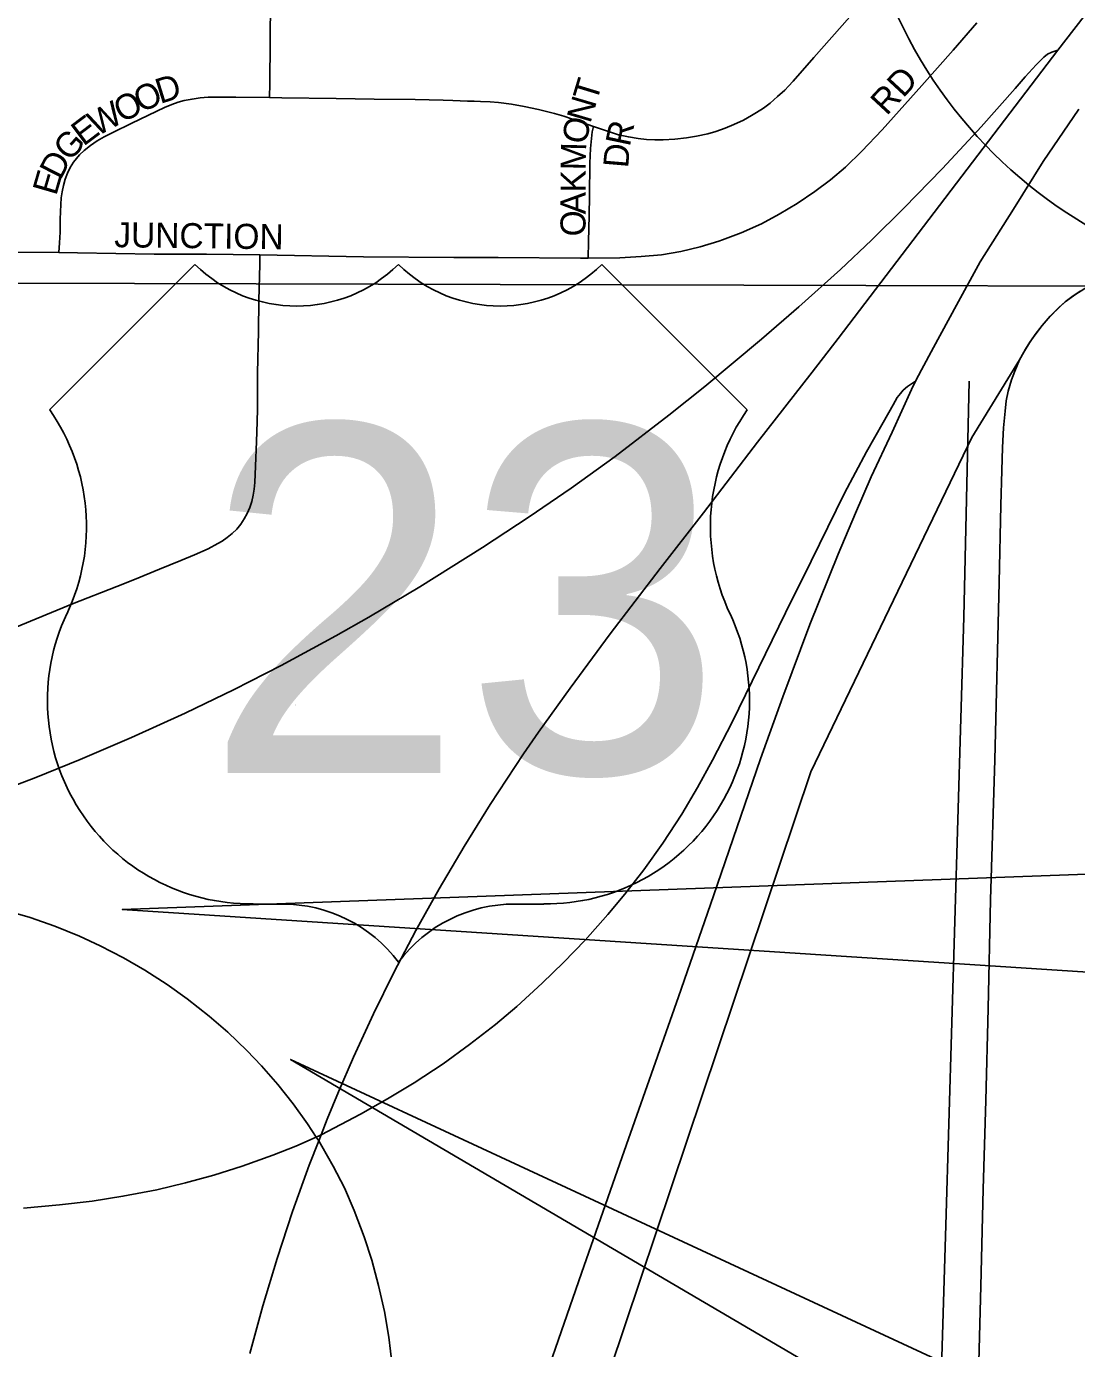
# Model space of a CAD drawing. Extents: x -5.6 to 34, y 0 to 22.
# Drawn here: x 5.62 to 6.458, y 18.084 to 19.139 of the extents above; entities that cross this region are included whole.
import ezdxf

# ---------------------------------------------------------------- set-up
doc = ezdxf.new("R2010")
doc.units = 0
for name, color, linetype in [('GM_X_City_Street', 7, 'Continuous'), ('GM_X_City_Street_Text', 7, 'Continuous'), ('GM_X_Corporation', 7, 'Continuous'), ('GM_X_Interstate_Route', 7, 'Continuous'), ('GM_X_Interstate_Shield', 7, 'Continuous'), ('GM_X_Minor_River', 7, 'Continuous'), ('GM_X_Section', 7, 'Continuous'), ('GM_X_Township_Road', 7, 'Continuous'), ('GM_X_US_Location', 7, 'Continuous'), ('GM_X_US_Route', 7, 'Continuous'), ('GM_X_US_Shield', 7, 'Continuous'), ('SH_Text', 7, 'Continuous')]:
    doc.layers.add(name, color=color, linetype=linetype)

msp = doc.modelspace()

# ---------------------------------------------------------------- linework, layer by layer
at = {"layer": 'GM_X_City_Street'}
for points in [[(5.8141, 19.0825), (5.8142, 19.0939), (5.8149, 19.1602), (5.8153, 19.1877), (5.8156, 19.1996), (5.8158, 19.204), (5.8162, 19.2074), (5.817, 19.2116), (5.8182, 19.2169), (5.8217, 19.2289)], [(6.0727, 19.0594), (6.0927, 19.0529), (6.1005, 19.0511), (6.1084, 19.0498), (6.115, 19.0491), (6.1217, 19.0488), (6.1284, 19.0489), (6.1376, 19.0494), (6.1469, 19.0504), (6.1548, 19.0517), (6.1639, 19.0536), (6.1703, 19.0554), (6.1777, 19.058), (6.1846, 19.0611), (6.1925, 19.0645), (6.1987, 19.0682), (6.2029, 19.0706), (6.2085, 19.0741), (6.2137, 19.0782), (6.2197, 19.0835), (6.2254, 19.0885), (6.2284, 19.0917), (6.2321, 19.0956), (6.2486, 19.1145), (6.2772, 19.147)], [(6.1727, 18.968), (6.1758, 18.9689), (6.1906, 18.9745), (6.2068, 18.9817), (6.2208, 18.9894), (6.2354, 18.998), (6.2495, 19.0075), (6.2619, 19.0169), (6.2738, 19.0271), (6.287, 19.0398), (6.3032, 19.0568), (6.3347, 19.0921), (6.3599, 19.1205), (6.3787, 19.1423)], [(5.6459, 18.9588), (5.6464, 18.9667), (5.6469, 18.975), (5.6469, 18.9855), (5.6473, 18.9972), (5.6477, 19.0024), (5.6484, 19.0074), (5.6495, 19.0124), (5.6509, 19.0173), (5.6527, 19.0221), (5.6549, 19.0267), (5.6575, 19.031), (5.6598, 19.034), (5.6623, 19.0368), (5.666, 19.0403), (5.671, 19.0442), (5.6763, 19.0479), (5.6819, 19.0511), (5.6888, 19.0547), (5.7042, 19.062), (5.7302, 19.0747), (5.7361, 19.0771), (5.741, 19.0788), (5.7459, 19.0801), (5.7522, 19.0814), (5.7586, 19.0823), (5.765, 19.0828), (5.7728, 19.083), (5.7872, 19.083), (5.8141, 19.0825)], [(5.8141, 19.0825), (5.8239, 19.0824), (5.8673, 19.0818), (5.8975, 19.0813), (5.9303, 19.0809), (5.9526, 19.0804), (5.9604, 19.0802), (5.9721, 19.0798), (5.9773, 19.0797), (5.9825, 19.0795), (5.9902, 19.0791), (5.9968, 19.0785), (6.0071, 19.0772), (6.0174, 19.0754), (6.0289, 19.073), (6.0415, 19.0698), (6.049, 19.0676), (6.0552, 19.0655), (6.0727, 19.0594)], [(6.0685, 18.9544), (6.0688, 18.9677), (6.0692, 18.9885), (6.0695, 19.0042), (6.0697, 19.0302), (6.0702, 19.0419), (6.071, 19.0498), (6.0717, 19.0552), (6.0727, 19.0594)], [(5.4879, 18.9598), (5.5036, 18.9596), (5.5431, 18.9597), (5.5844, 18.9592), (5.6459, 18.9588)], [(5.6459, 18.9588), (5.6607, 18.9587), (5.722, 18.9576), (5.7636, 18.9576), (5.8064, 18.9569)], [(6.0685, 18.9544), (6.0937, 18.9547), (6.1107, 18.9556), (6.1271, 18.957), (6.1424, 18.9597), (6.1578, 18.9634), (6.1727, 18.968)], [(5.5984, 18.6544), (5.6567, 18.6783), (5.6922, 18.6921), (5.7063, 18.6979), (5.7262, 18.706), (5.7432, 18.7129), (5.754, 18.7174), (5.765, 18.7224), (5.7728, 18.7266), (5.7761, 18.7284), (5.7803, 18.7312), (5.7843, 18.7344), (5.7879, 18.738), (5.7911, 18.7419), (5.7939, 18.7461), (5.7963, 18.7505), (5.7982, 18.7552), (5.7998, 18.76), (5.801, 18.765), (5.8019, 18.77), (5.8023, 18.7751), (5.8027, 18.7882), (5.8037, 18.8079), (5.8041, 18.8236), (5.8043, 18.834), (5.8045, 18.8629), (5.8053, 18.8957), (5.8056, 18.9206), (5.8062, 18.9495), (5.8064, 18.9569)], [(5.8064, 18.9569), (5.8891, 18.9555), (5.9612, 18.9548), (5.9967, 18.9549), (6.0623, 18.9543), (6.0685, 18.9544)]]:
    msp.add_lwpolyline(points, dxfattribs=at)
at = {"layer": 'GM_X_Corporation'}
msp.add_lwpolyline([(6.0731, 18.0291), (6.2463, 18.5443), (6.3746, 18.8111), (6.4129, 18.8731), (6.4177, 18.8818), (6.421, 18.8872), (6.4242, 18.8919), (6.4309, 18.9006), (6.4373, 18.908), (6.4449, 18.9155), (6.4493, 18.9194), (6.4578, 18.9257), (6.4691, 18.9327)], dxfattribs=at)
at = {"layer": 'GM_X_Interstate_Route'}
for points in [[(6.4434, 19.1203), (6.5045, 19.1998), (6.6774, 19.4249), (6.728, 19.4903), (6.7458, 19.5147), (6.7571, 19.5292), (6.7812, 19.5604), (6.8077, 19.5946), (6.8489, 19.6491), (6.8692, 19.6749), (6.8764, 19.6843), (6.9676, 19.803), (6.9901, 19.832), (7.0116, 19.8603), (7.0636, 19.928), (7.1256, 20.0079), (7.151, 20.0413), (7.1916, 20.0946), (7.2051, 20.1124), (7.2499, 20.1707), (7.2925, 20.2258), (7.3849, 20.342)], [(5.7982, 18.0799), (5.8086, 18.1179), (5.8201, 18.1556), (5.8324, 18.1931), (5.8458, 18.2302), (5.8533, 18.2495), (5.8552, 18.2545), (5.86, 18.2669), (5.8691, 18.2887), (5.8811, 18.3164), (5.897, 18.3509), (5.9132, 18.3839), (5.9308, 18.4176), (5.9494, 18.4508), (5.9694, 18.4847), (5.9902, 18.5181), (6.0169, 18.5586), (6.0288, 18.5759), (6.054, 18.6111), (6.086, 18.6543), (6.1258, 18.7065), (6.1606, 18.751), (6.2037, 18.8073), (6.2472, 18.8633), (6.268, 18.8903), (6.4434, 19.1203)], [(6.3298, 18.856), (6.3346, 18.8653), (6.3442, 18.8829), (6.3626, 18.9167), (6.3815, 18.9514), (6.4079, 18.9935), (6.4316, 19.0315), (6.4602, 19.0733)], [(6.0193, 18.0173), (6.0631, 18.1439), (6.0955, 18.2369), (6.1406, 18.3645), (6.1685, 18.4452), (6.2061, 18.5546), (6.2238, 18.604), (6.2455, 18.6619), (6.2679, 18.718), (6.2818, 18.7507), (6.2943, 18.7797), (6.3111, 18.8154), (6.3265, 18.8496), (6.3298, 18.856)], [(5.912, 18.0706), (5.9092, 18.0928), (5.9057, 18.1135), (5.9011, 18.134), (5.8956, 18.1543), (5.8896, 18.173), (5.8816, 18.1939), (5.8738, 18.212), (5.8649, 18.2295), (5.8558, 18.2455), (5.8533, 18.2495), (5.8512, 18.2526), (5.8444, 18.2632), (5.8329, 18.2792), (5.8206, 18.2945), (5.8077, 18.3094), (5.7959, 18.3218), (5.7807, 18.3363), (5.7658, 18.3492), (5.7482, 18.3629), (5.7322, 18.3744), (5.7145, 18.3858), (5.6975, 18.3957), (5.6789, 18.4053), (5.6622, 18.413), (5.6427, 18.4209), (5.6229, 18.4278), (5.6028, 18.4338)]]:
    msp.add_lwpolyline(points, dxfattribs=at)
at = {"layer": 'GM_X_Interstate_Shield'}
msp.add_arc((6.6563, 19.304), 0.375, 165.8066, 258.463, dxfattribs=at)
at = {"layer": 'GM_X_Minor_River'}
msp.add_lwpolyline([(6.3107, 14.9085), (6.3148, 15.2836), (6.3128, 15.6243), (6.3166, 15.7268), (6.3177, 16.1789), (6.3167, 16.5989), (6.3206, 16.7696), (6.3343, 17.2728), (6.3403, 17.7344), (6.3541, 18.1823), (6.3684, 18.6678), (6.3725, 18.8561)], dxfattribs=at)
at = {"layer": 'GM_X_Section'}
for points in [[(7.5006, 20.9), (7.2498, 20.9), (7.2609, 20.8761), (5.343, 19.9706), (5.3166, 18.9352), (7.4578, 18.9294)], [(5.3166, 18.9352), (7.4578, 18.9294), (7.4183, 16.7871), (5.2895, 16.8144)]]:
    msp.add_lwpolyline(points, close=True, dxfattribs=at)
at = {"layer": 'GM_X_Township_Road'}
for points in [[(6.4129, 18.8731), (6.4162, 18.8792), (6.4207, 18.8868), (6.4252, 18.8933), (6.4309, 18.9006), (6.4369, 18.9076), (6.4443, 18.915), (6.4493, 18.9194), (6.4545, 18.9234), (6.4611, 18.9279)], [(6.3803, 18.0732), (6.3819, 18.1336), (6.3838, 18.211), (6.3859, 18.2819), (6.3879, 18.3554), (6.3897, 18.4421), (6.393, 18.5537), (6.3965, 18.6955), (6.3979, 18.7572), (6.3987, 18.7848), (6.3993, 18.8032), (6.4001, 18.819), (6.4013, 18.8322), (6.4021, 18.8405), (6.4038, 18.8482), (6.4065, 18.8572), (6.409, 18.864), (6.4129, 18.8731)]]:
    msp.add_lwpolyline(points, dxfattribs=at)
at = {"layer": 'GM_X_US_Route'}
for points in [[(6.4434, 19.1203), (6.4385, 19.1188), (6.4351, 19.1172), (6.4322, 19.1149), (6.4262, 19.1087), (6.4173, 19.0991), (6.4093, 19.0897), (6.3823, 19.0592), (6.3583, 19.0335)], [(6.3583, 19.0335), (6.351, 19.0256), (6.3208, 18.9945), (6.2947, 18.9687), (6.2698, 18.9453), (6.2367, 18.9154), (6.2069, 18.8896), (6.1615, 18.8518), (6.1328, 18.8289), (6.0901, 18.7961), (6.0549, 18.7708), (6.0213, 18.7479), (5.9841, 18.7233), (5.934, 18.692), (5.8934, 18.6678), (5.8671, 18.6528), (5.8233, 18.6291), (5.7859, 18.61), (5.7468, 18.5912), (5.7038, 18.5716), (5.6628, 18.554), (5.6275, 18.5397), (5.5846, 18.5234)], [(6.3298, 18.856), (6.3233, 18.8518), (6.3198, 18.8489), (6.3177, 18.8464), (6.3152, 18.843), (6.3119, 18.8372), (6.304, 18.8232), (6.2906, 18.7997), (6.2732, 18.7668), (6.2464, 18.7124), (6.226, 18.6712), (6.1833, 18.5839), (6.1677, 18.5536), (6.1558, 18.5318), (6.1431, 18.5104), (6.1281, 18.4874), (6.1128, 18.4661), (6.0976, 18.4465), (6.0842, 18.4304), (6.0659, 18.4098), (6.0487, 18.3919), (6.0318, 18.3754), (6.0115, 18.3569), (5.9945, 18.3426), (5.9738, 18.3265), (5.9526, 18.3111), (5.9296, 18.296), (5.9083, 18.2831), (5.8866, 18.2709), (5.8552, 18.2545), (5.8542, 18.2539), (5.8512, 18.2526), (5.835, 18.2455), (5.8168, 18.2381), (5.7921, 18.2294), (5.7697, 18.2222), (5.7469, 18.216), (5.724, 18.2106), (5.697, 18.2054), (5.6724, 18.2015), (5.6464, 18.1984), (5.6177, 18.196)]]:
    msp.add_lwpolyline(points, dxfattribs=at)
at = {"layer": 'GM_X_US_Shield'}
for p, q in [((5.7545, 18.9492), (5.6385, 18.8332)), ((6.1954, 18.8332), (6.0794, 18.9492)), ((5.8009, 18.4387), (5.8241, 18.4387)), ((6.0098, 18.4387), (6.033, 18.4387))]:
    msp.add_line(p, q, dxfattribs=at)
for centre, radius, start, end in [((5.8357, 19.0321), 0.116, 225.573, 314.427), ((5.9982, 19.0321), 0.116, 225.573, 314.427), ((5.5055, 18.74), 0.1624, 334.5471, 35.0009), ((6.3284, 18.74), 0.1624, 144.9991, 205.4529), ((5.7991, 18.6012), 0.1624, 154.8319, 270.6383), ((6.0348, 18.6012), 0.1624, 269.3617, 25.1681), ((5.8241, 18.3227), 0.116, 36.8699, 90), ((6.0098, 18.3227), 0.116, 90, 143.1301)]:
    msp.add_arc(centre, radius, start, end, dxfattribs=at)
at = {"layer": 'SH_Text'}
for points in [[(10.6219, 18.1148), (5.6964, 18.4344), (10.6219, 18.6148)], [(9.909, 15.9208), (5.8309, 18.3146), (9.909, 16.4208)]]:
    msp.add_lwpolyline(points, close=True, dxfattribs=at)

# ---------------------------------------------------------------- texts
at = {"layer": 'GM_X_City_Street_Text'}
for s, rotation, p in [('D', 17.2393, (5.7267, 19.0774)), ('T', 73.0861, (6.0751, 19.0782)), ('RD', 47.1283, (6.3067, 19.0675)), ('O', 27.1417, (5.6961, 19.062)), ('O', 26.0666, (5.7117, 19.07)), ('W', 28.3474, (5.6761, 19.0512)), ('N', 73.4661, (6.0701, 19.0613)), ('E', 36.9956, (5.6655, 19.0432)), ('O', 78.7158, (6.0668, 19.0445)), ('R', 78.1614, (6.1016, 19.0428)), ('G', 48.0924, (5.6545, 19.0308)), ('M', 88.6885, (6.0664, 19.0243)), ('D', 85.2073, (6.1003, 19.0259)), ('D', 62.9072, (5.6473, 19.0162)), ('E', 73.7769, (5.6437, 19.0036)), ('K', 89.8688, (6.0664, 19.0068)), ('A', 89.8688, (6.0663, 18.9893)), ('O', 89.8688, (6.0663, 18.9717)), ('JUNCTION', 359.2652, (5.69, 18.9631))]:
    msp.add_text(s, height=0.02, rotation=rotation, dxfattribs=at).set_placement(p)
at = {"layer": 'GM_X_US_Location'}
for s in ['0', '/']:
    msp.add_text(s, height=0.0004, dxfattribs=at).set_placement((5.9168, 18.6802))
msp.add_text('23', height=0.0004, rotation=0, dxfattribs=at).set_placement((5.8342, 18.5974))
at = {"layer": 'GM_X_US_Shield'}
msp.add_text('23', height=0.27844, dxfattribs=at).set_placement((5.762, 18.5432))

doc.saveas('drawing.dxf')
